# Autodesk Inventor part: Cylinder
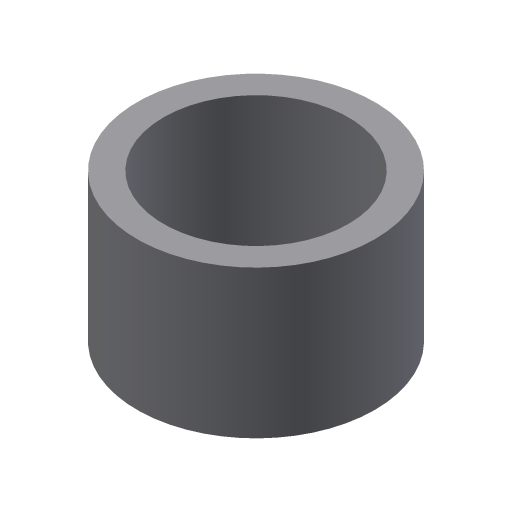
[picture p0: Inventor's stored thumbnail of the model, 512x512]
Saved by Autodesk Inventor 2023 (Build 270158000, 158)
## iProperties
Part Number: Cylinder
Document SubType Name: Modeling
Created: 2003-01
Designer: Owner
Density: 1 g/cm^3
Material: Generic
Appearance: Default
Control State: 0
Master: False
Checked Out: False
Shininess: 64.0
Length Units: 11269
Angle Units: 11279
Time Units: 11290
Mass Units: 11283
Length Display Precision: 3
Angle Display Precision: 2
Compacted: True
Density: 0.0
Volumn: 0.0
Area: 0.0
PropertySet Name: Model Information
Author: Owner
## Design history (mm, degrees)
sketch "Sketch1"
  geometry: C1 r 112.5 at (0, 0); C2 r 87.5 at (0, 0)
  constraints: 2 centre point, 1 coincident, 1 concentric
  dimensions: "d0" = 225 diameter of C1; "d1" = 175 diameter of C2
extrude "Extrusion1" new body sketch "Sketch1" stored distance "d2" = 140; taper "d3" = 0 deg
body "Solid1"
